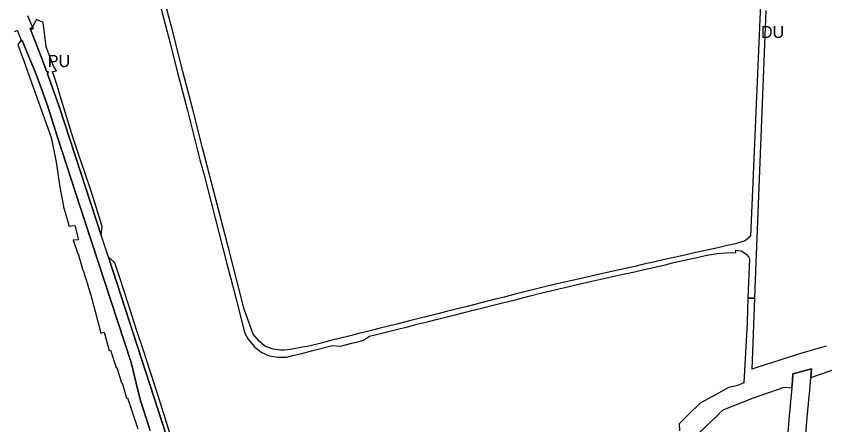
# Model space of a CAD drawing. Extents: x -521047 to -518054, y -1194945 to -1189555.
# Drawn here: x -520307 to -519638, y -1191028 to -1190690 of the extents above; entities that cross this region are included whole.
import ezdxf

# ---------------------------------------------------------------- set-up
doc = ezdxf.new("R2010")
doc.units = 0
for name, color, linetype in [('90310013', 7, 'Continuous'), ('90320013', 7, 'Continuous'), ('90450013', 7, 'Continuous'), ('90450023', 7, 'Continuous')]:
    doc.layers.add(name, color=color, linetype=linetype)

msp = doc.modelspace()

# ---------------------------------------------------------------- linework, layer by layer
at = {"layer": '90310013'}
for points in [[(-519689.17, -1190630.58), (-519691.85, -1190693.04), (-519699.53, -1190872.03), (-519704.17, -1190875.86), (-519712.1, -1190878.14), (-519720.01, -1190879.91), (-519726.71, -1190881.45), (-519735.48, -1190883.39), (-519744.82, -1190885.5), (-519753.88, -1190887.53), (-519761.74, -1190889.28), (-519770.59, -1190891.25), (-519778.65, -1190893.08), (-519787.9, -1190895.13), (-519795.35, -1190896.85), (-519803.05, -1190898.55), (-519818.11, -1190901.93), (-519848.19, -1190908.66), (-519860.73, -1190911.52), (-519871.99, -1190914.33), (-519895.15, -1190920.15), (-519903.31, -1190922.21), (-519911.52, -1190924.24), (-519919.3, -1190926.24), (-519927.39, -1190928.23), (-519934.89, -1190930.13), (-519943.05, -1190932.07), (-519951.02, -1190934.14), (-519958.21, -1190935.99), (-519965.83, -1190937.89), (-519974.87, -1190940.16), (-519982.65, -1190942.1), (-519991.99, -1190944.47), (-520006.72, -1190948.17), (-520014.15, -1190950.02), (-520022.16, -1190952.02), (-520031.59, -1190954.41), (-520039.61, -1190956.43), (-520047.59, -1190958.43), (-520055.65, -1190960.44), (-520062.47, -1190962.13), (-520066.19, -1190963.08), (-520069.92, -1190963.7), (-520079.75, -1190965.36), (-520085.19, -1190966.03), (-520087.88, -1190966), (-520094.18, -1190965.2), (-520101.06, -1190962.64), (-520105.42, -1190959.01), (-520110.62, -1190952.85), (-520118.11, -1190932.22), (-520130.36, -1190884.81), (-520143.17, -1190835.12), (-520152.5, -1190799.08), (-520160.7, -1190767.16), (-520168.76, -1190735.95), (-520171.9, -1190723.98), (-520175.07, -1190711.67), (-520177.82, -1190700.89), (-520180.5, -1190690.67), (-520185.7, -1190670.28)], [(-520190.1, -1190671.19), (-520184.89, -1190691.51), (-520182.14, -1190702.16), (-520179.47, -1190712.51), (-520176.29, -1190724.77), (-520173.21, -1190736.7), (-520165.15, -1190767.99), (-520154.72, -1190808.75), (-520151.61, -1190820.43), (-520148.53, -1190832.37), (-520132.72, -1190893.53), (-520124.37, -1190925.82), (-520117.77, -1190951.37), (-520114.88, -1190956.87), (-520109.65, -1190963.19), (-520104.07, -1190967.71), (-520097.48, -1190970.69), (-520090.37, -1190971.94), (-520085.31, -1190971.83), (-520083.18, -1190971.78), (-520077.83, -1190970.45), (-520070.6, -1190968.71), (-520062.63, -1190966.61), (-520055.99, -1190964.97), (-520047.4, -1190962.76), (-520045.1, -1190962.2), (-520038.54, -1190962.66), (-520030.34, -1190960.58), (-520022.33, -1190958.55), (-520019.58, -1190957.88), (-520014.63, -1190954.57), (-520006.62, -1190952.57), (-519992.34, -1190949.01), (-519983.03, -1190946.64), (-519975.1, -1190944.67), (-519965.72, -1190942.29), (-519958.33, -1190940.45), (-519950.59, -1190938.53), (-519942.63, -1190936.51), (-519935.17, -1190934.6), (-519927.66, -1190932.75), (-519919.76, -1190930.76), (-519911.36, -1190928.66), (-519903.58, -1190926.7), (-519895.36, -1190924.64), (-519881.75, -1190921.22), (-519872.14, -1190918.8), (-519861.35, -1190916.11), (-519848.52, -1190913.15), (-519842.5, -1190911.8), (-519830.75, -1190909.18), (-519818.3, -1190906.39), (-519803.46, -1190903.12), (-519795.54, -1190901.33), (-519787.54, -1190899.54), (-519778.8, -1190897.57), (-519770.26, -1190895.53), (-519761.88, -1190893.5), (-519754.32, -1190891.81), (-519745.1, -1190889.75), (-519735.59, -1190887.67), (-519726.78, -1190886.09), (-519720, -1190885.58), (-519711.68, -1190885.43), (-519711.68, -1190883.58), (-519710.16, -1190883.6), (-519707.32, -1190884.15), (-519705.1, -1190885.35), (-519703.03, -1190887.15), (-519701.34, -1190889.07), (-519700.57, -1190890.69), (-519701.74, -1190923.21), (-519698.85, -1190923.21), (-519695.96, -1190923.2), (-519694.83, -1190893.33), (-519694.59, -1190887.19), (-519687.84, -1190713.61), (-519686.8, -1190685.4)]]:
    msp.add_lwpolyline(points, dxfattribs=at)
at = {"layer": '90320013'}
for points in [[(-520182.63, -1191035.95), (-520230.16, -1190890.07), (-520236.36, -1190871.04), (-520240.76, -1190857.54), (-520262.17, -1190791.69), (-520270.77, -1190765.71), (-520280.68, -1190737.8), (-520280.2, -1190736.19), (-520281.23, -1190736.32), (-520285.87, -1190723.9), (-520295.08, -1190700.37), (-520294.01, -1190699.91), (-520293.63, -1190700.88), (-520292.48, -1190700.46), (-520293.09, -1190699.05), (-520293.32, -1190698.51), (-520294.84, -1190695.28), (-520297.09, -1190690.03)], [(-520308.05, -1190702.75), (-520305.81, -1190701.95), (-520305.63, -1190702.37), (-520303.5, -1190707.28), (-520302.42, -1190709.94), (-520302.14, -1190710.64), (-520301.61, -1190710.41), (-520290.46, -1190737.48), (-520285.79, -1190750.09), (-520280.58, -1190764.7), (-520272.75, -1190789.2), (-520249.8, -1190859.62), (-520211.72, -1190976.35), (-520207.32, -1190993.25), (-520204.26, -1191006.85), (-520195.92, -1191032.27)]]:
    msp.add_lwpolyline(points, dxfattribs=at)
at = {"layer": '90450013'}
for points in [[(-520293.09, -1190699.05), (-520292.48, -1190700.46), (-520293.63, -1190700.88), (-520294.01, -1190699.91), (-520295.08, -1190700.37), (-520285.87, -1190723.9), (-520281.23, -1190736.32), (-520280.2, -1190736.19), (-520280.68, -1190737.8), (-520270.77, -1190765.71), (-520262.17, -1190791.69), (-520240.76, -1190857.54), (-520236.36, -1190871.04), (-520235.43, -1190864), (-520238.06, -1190855.91), (-520241.74, -1190844.48), (-520245.31, -1190833.02), (-520249.99, -1190819.22), (-520254.71, -1190805.08), (-520259.46, -1190790.98), (-520263.86, -1190776.71), (-520269.42, -1190758.67), (-520272.84, -1190747.57), (-520276.48, -1190735.78), (-520273.18, -1190735.42), (-520275.82, -1190731.46), (-520278, -1190725.72), (-520281.82, -1190715.67), (-520284.45, -1190695.5), (-520289.87, -1190692.86), (-520293.09, -1190699.05)], [(-520195.92, -1191032.27), (-520204.26, -1191006.85), (-520207.32, -1190993.25), (-520211.72, -1190976.35), (-520249.8, -1190859.62), (-520272.75, -1190789.2), (-520280.58, -1190764.7), (-520285.79, -1190750.09), (-520290.46, -1190737.48), (-520301.61, -1190710.41), (-520302.14, -1190710.64), (-520302.42, -1190709.94), (-520305.27, -1190713.64), (-520302.99, -1190719.99), (-520300.71, -1190726.33), (-520296.43, -1190738.23), (-520277.63, -1190790.53), (-520273.53, -1190810.79), (-520270.52, -1190831.41), (-520267.5, -1190847.21), (-520267.39, -1190847.59), (-520263.2, -1190862.84), (-520262.98, -1190863.56), (-520258.02, -1190863.1), (-520255.08, -1190874.8), (-520259.39, -1190875.3), (-520255.71, -1190886.45), (-520255.51, -1190886.39), (-520251.59, -1190899.9), (-520251.4, -1190899.87), (-520251.31, -1190900.17), (-520247.73, -1190911.63), (-520244.95, -1190920.5), (-520240.61, -1190937.16), (-520236.53, -1190951.96), (-520233.93, -1190951.28), (-520229.77, -1190966.31), (-520228.78, -1190966.1), (-520223.88, -1190980.31), (-520223.44, -1190980.23), (-520219.46, -1190993.07), (-520219.11, -1190993.01), (-520215.38, -1191005.75), (-520214.59, -1191005.55), (-520210.43, -1191017.92), (-520206.21, -1191031.01)], [(-520177.92, -1191040.13), (-520182.12, -1191026.63), (-520186.01, -1191014.15), (-520189.52, -1191002.89), (-520190.94, -1190998.56), (-520196.19, -1190982.5), (-520201.44, -1190966.42), (-520207.32, -1190948.31), (-520212.13, -1190933.49), (-520217.11, -1190918.22), (-520221.78, -1190903.95), (-520225.02, -1190894.03), (-520229.39, -1190889.84), (-520230.16, -1190890.07), (-520182.63, -1191035.95)], [(-519637.19, -1190962.65), (-519654.44, -1190967.68), (-519659.92, -1190969.28), (-519674.43, -1190973.99), (-519695.12, -1190980.71), (-519698.16, -1190981.7), (-519695.96, -1190923.2), (-519698.85, -1190923.21), (-519701.74, -1190923.21), (-519702.46, -1190943.23), (-519705.25, -1190993.14), (-519710.38, -1190995.17), (-519718.32, -1190997.18), (-519725.58, -1191001.15), (-519741.25, -1191009.72), (-519750.67, -1191019), (-519758.73, -1191026.94), (-519758.39, -1191032.67)], [(-519742.58, -1191034.77), (-519725.84, -1191018.93), (-519725.85, -1191018.51), (-519722.26, -1191015.24), (-519718.08, -1191013.61), (-519697.01, -1191005.37), (-519671.83, -1190996.5), (-519665.55, -1190997.17), (-519665.04, -1190991.42), (-519664.52, -1190985.67), (-519649.09, -1190981.52), (-519649.41, -1190985.12), (-519649.73, -1190988.71), (-519626.59, -1190980.56)]]:
    msp.add_lwpolyline(points, dxfattribs=at)
at = {"layer": '90450023'}
msp.add_lwpolyline([(-519654.53, -1191041.95), (-519652.71, -1191021.78), (-519651.65, -1191010.05), (-519650.63, -1190998.76), (-519649.73, -1190988.71), (-519649.41, -1190985.12), (-519649.09, -1190981.52), (-519664.52, -1190985.67), (-519665.04, -1190991.42), (-519665.55, -1190997.17), (-519667.64, -1191020.37), (-519669.45, -1191040.49)], dxfattribs=at)

# ---------------------------------------------------------------- texts
at = {"layer": '90310013'}
msp.add_text('DU', height=10, rotation=360, dxfattribs=at).set_placement((-519691.05, -1190708.23))
at = {"layer": '90450013'}
msp.add_text('PU', height=10, rotation=360, dxfattribs=at).set_placement((-520280.57, -1190732.29))

doc.saveas('drawing.dxf')
